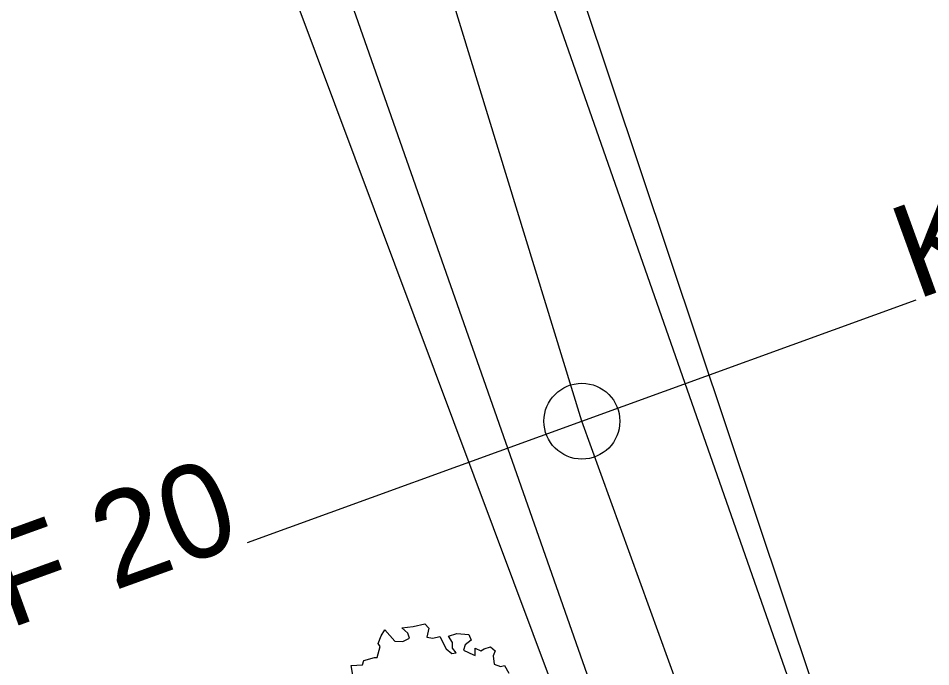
# Model space of a CAD drawing. Extents: x -475575 to -473225, y -1116053 to -1114104.
# Drawn here: x -474299.39 to -474280.15, y -1114815.43 to -1114801.75 of the extents above; entities that cross this region are included whole.
import ezdxf

# ---------------------------------------------------------------- set-up
doc = ezdxf.new("R2010")
doc.units = 0
for name, color, linetype in [('CESTN___P____KOP_N__VRH__Construction_', 7, 'Continuous'), ('IP', 7, 'Continuous'), ('POLYGONY_SITUACE_PF', 7, 'Continuous'), ('POLYGONY_SITUACE_PF_POPISY', 7, 'Continuous'), ('POLYGONY_SITUACE_PO', 7, 'Continuous'), ('Vrstevnice_vedlejsi', 7, 'Continuous')]:
    doc.layers.add(name, color=color, linetype=linetype)

msp = doc.modelspace()

# ---------------------------------------------------------------- linework, layer by layer
at = {"layer": 'CESTN___P____KOP_N__VRH__Construction_'}
for p, q in [((-474276.446, -1114834.295), (-474288.437, -1114798.457)), ((-474289.112, -1114798.644), (-474275.951, -1114836.244)), ((-474294.043, -1114800.011), (-474280.644, -1114835.818))]:
    msp.add_line(p, q, dxfattribs=at)
msp.add_lwpolyline([(-474292.967, -1114799.713), (-474278.348, -1114841.367)], dxfattribs=at)
at = {"layer": 'IP'}
msp.add_lwpolyline([(-474292.328, -1114815.645), (-474292.372, -1114815.4), (-474292.128, -1114815.384), (-474292.1, -1114815.295), (-474291.876, -1114815.232), (-474291.823, -1114815.233), (-474291.76, -1114815.002), (-474291.799, -1114814.935), (-474291.74, -1114814.777), (-474291.66, -1114814.651), (-474291.45, -1114814.887), (-474291.283, -1114814.894), (-474291.141, -1114814.826), (-474291.176, -1114814.717), (-474291.303, -1114814.61), (-474291.064, -1114814.579), (-474290.818, -1114814.52), (-474290.731, -1114814.617), (-474290.772, -1114814.806), (-474290.648, -1114814.825), (-474290.497, -1114814.793), (-474290.364, -1114815.05), (-474290.25, -1114815.148), (-474290.155, -1114815.131), (-474290.233, -1114815.033), (-474290.232, -1114814.919), (-474290.317, -1114814.784), (-474290.142, -1114814.729), (-474289.89, -1114814.745), (-474289.841, -1114814.865), (-474289.962, -1114814.967), (-474290.002, -1114815.076), (-474289.791, -1114815.179), (-474289.756, -1114815.189), (-474289.753, -1114815.034), (-474289.636, -1114815.092), (-474289.562, -1114815.048), (-474289.432, -1114815.005), (-474289.33, -1114815.095), (-474289.374, -1114815.198), (-474289.357, -1114815.376), (-474289.219, -1114815.421), (-474289.133, -1114815.403), (-474289.045, -1114815.561)], dxfattribs=at)
at = {"layer": 'POLYGONY_SITUACE_PF'}
msp.add_lwpolyline([(-474294.555, -1114812.806), (-474287.504, -1114810.25), (-474280.454, -1114807.693)], dxfattribs=at)
at = {"layer": 'POLYGONY_SITUACE_PO'}
msp.add_lwpolyline([(-474033.93, -1115484.017), (-474028.81, -1115469.55), (-474027.706, -1115465.586), (-474027.155, -1115461.509), (-474027.167, -1115457.394), (-474027.702, -1115449.947), (-474028.133, -1115446.706), (-474028.952, -1115443.542), (-474030.148, -1115440.499), (-474155.776, -1115170.193), (-474159.336, -1115162.232), (-474162.663, -1115154.172), (-474165.754, -1115146.018), (-474287.504, -1114810.25), (-474291.915, -1114795.876)], dxfattribs=at)
msp.add_circle((-474287.504, -1114810.25), 0.8, dxfattribs=at)
at = {"layer": 'Vrstevnice_vedlejsi'}
msp.add_spline([(-474437.042, -1114819.293), (-474434.084, -1114825.209), (-474430.367, -1114830.139), (-474425.892, -1114834.084), (-474420.658, -1114837.042), (-474416.092, -1114839.651), (-474412.193, -1114841.91), (-474408.961, -1114843.819), (-474406.17, -1114845.175), (-474403.819, -1114845.976), (-474401.91, -1114846.222), (-474399.894, -1114846.41), (-474397.772, -1114846.54), (-474395.544, -1114846.612), (-474392.326, -1114845.917), (-474388.117, -1114844.456), (-474382.919, -1114842.228), (-474377.635, -1114840.328), (-474372.267, -1114838.756), (-474366.814, -1114837.513), (-474363.095, -1114836.667), (-474361.109, -1114836.218), (-474360.858, -1114836.166), (-474360.556, -1114836.02), (-474360.203, -1114835.777), (-474359.801, -1114835.439), (-474359.332, -1114834.968), (-474358.797, -1114834.361), (-474358.196, -1114833.621), (-474354.891, -1114832.001), (-474348.88, -1114829.5), (-474340.165, -1114826.12), (-474334.156, -1114822.869), (-474330.854, -1114819.748), (-474330.259, -1114816.757), (-474329.115, -1114813.187), (-474327.422, -1114809.038), (-474325.181, -1114804.31), (-474323.7, -1114800.992), (-474322.978, -1114799.083), (-474323.016, -1114798.585), (-474323.033, -1114797.93), (-474323.031, -1114797.117), (-474323.009, -1114796.147), (-474323.155, -1114794.732), (-474323.468, -1114792.874), (-474323.949, -1114790.572), (-474324.49, -1114787.628), (-474325.092, -1114784.045), (-474325.755, -1114779.82), (-474326.209, -1114775.273), (-474326.456, -1114770.405), (-474326.495, -1114765.214), (-474326.14, -1114761.385), (-474325.39, -1114758.918), (-474324.245, -1114757.812), (-474323.137, -1114756.635), (-474322.067, -1114755.386), (-474321.033, -1114754.064), (-474318.524, -1114751.267), (-474314.539, -1114746.995), (-474309.078, -1114741.247), (-474304.962, -1114736.723), (-474302.19, -1114733.423), (-474300.762, -1114731.348), (-474298.898, -1114729.218), (-474296.597, -1114727.033), (-474293.86, -1114724.793), (-474291.297, -1114722.617), (-474288.909, -1114720.504), (-474286.695, -1114718.455), (-474285.096, -1114716.881), (-474284.112, -1114715.782), (-474283.742, -1114715.158), (-474283.12, -1114714.083), (-474282.248, -1114712.559), (-474281.124, -1114710.584), (-474277.593, -1114706.088), (-474271.656, -1114699.072), (-474263.312, -1114689.536), (-474256.985, -1114681.99), (-474252.676, -1114676.435), (-474250.384, -1114672.87), (-474248.437, -1114669.822), (-474246.835, -1114667.291), (-474245.578, -1114665.276), (-474244.259, -1114663.746), (-474242.88, -1114662.7), (-474241.44, -1114662.139), (-474237.363, -1114662.485), (-474230.649, -1114663.736), (-474221.299, -1114665.894), (-474213.737, -1114667.185), (-474207.965, -1114667.609), (-474203.983, -1114667.167), (-474200.774, -1114667.794), (-474198.341, -1114669.49)], degree=3, dxfattribs=at)

# ---------------------------------------------------------------- texts
at = {"layer": 'POLYGONY_SITUACE_PF_POPISY'}
for s, p in [('KM=0.726', (-474280.465, -1114807.697)), ('PF 20', (-474301.244, -1114815.232))]:
    msp.add_text(s, height=1.9765, rotation=19.9307, dxfattribs=at).set_placement(p)

doc.saveas('drawing.dxf')
